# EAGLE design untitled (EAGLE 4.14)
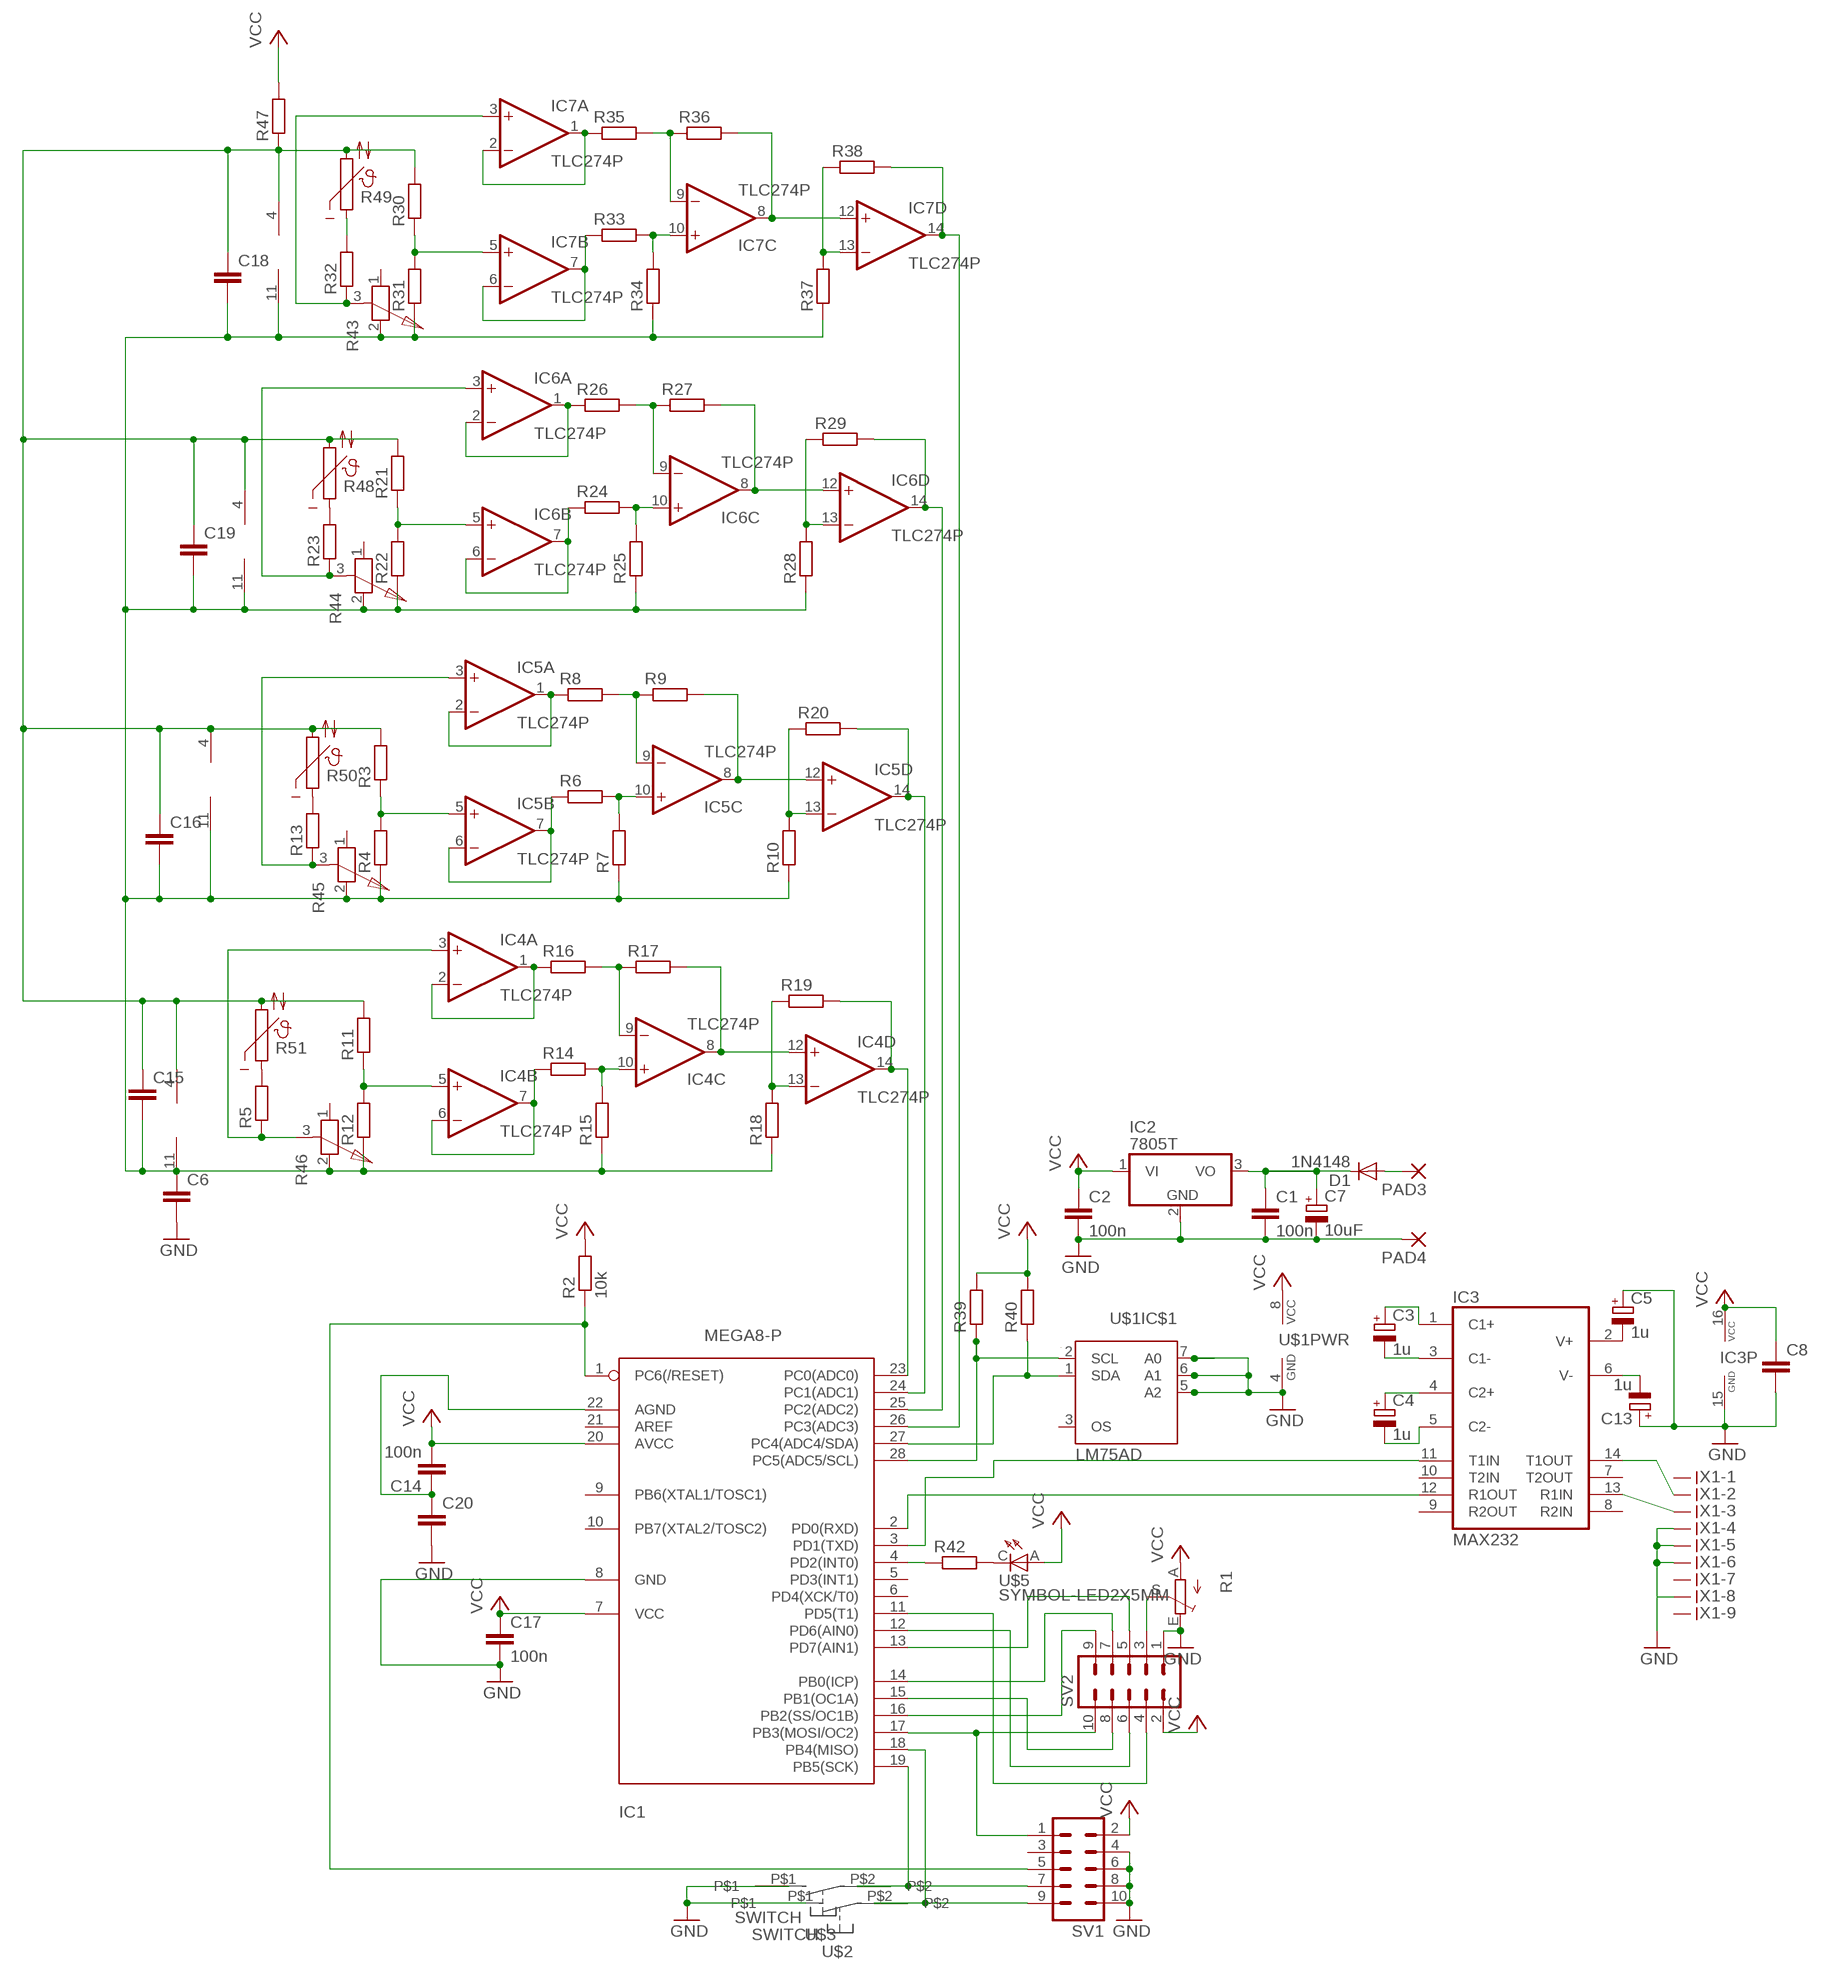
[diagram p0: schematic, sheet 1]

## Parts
C1  100n  C-EUC0805  [C0805]
C2  100n  C-EUC0805  [C0805]
C3  1u  CPOL-EUE2.5-5  [E2,5-5]
C4  1u  CPOL-EUE2.5-5  [E2,5-5]
C5  1u  CPOL-EUE2.5-5  [E2,5-5]
C6  C-EUC0402  [C0402]
C7  10uF  CPOL-EUE5-10.5  [E5-10,5]
C8  C-EUC0805  [C0805]
C13  1u  CPOL-EUE2.5-5  [E2,5-5]
C14  100n  C-EUC0805  [C0805]
C15  C-EUC0805  [C0805]
C16  C-EUC0805  [C0805]
C17  100n  C-EUC0805  [C0805]
C18  C-EUC0805  [C0805]
C19  C-EUC0805  [C0805]
C20  C-EUC0402  [C0402]
D1  1N4148  [DO35-10]
IC1  MEGA8-P  [DIL28-3]
IC2  7805T  [TO220H]
IC3  MAX232  [DIL16]
IC4  TLC274P  [DIL14]
IC5  TLC274P  [DIL14]
IC6  TLC274P  [DIL14]
IC7  TLC274P  [DIL14]
PAD3  3,81/1,4  [3,81/1,4]
PAD4  3,81/1,4  [3,81/1,4]
R1  TRIM_EU-LI10  [LI10]
R2  10k  R-EU_R1206  [R1206]
R3  R-EU_R1206W  [R1206W]
R4  R-EU_R1206W  [R1206W]
R5  R-EU_R1206  [R1206]
R6  R-EU_0309/10  [0309/10]
R7  R-EU_0309/10  [0309/10]
R8  R-EU_0309/10  [0309/10]
R9  R-EU_0309/10  [0309/10]
R10  R-EU_0309/10  [0309/10]
R11  R-EU_R1206W  [R1206W]
R12  R-EU_R1206W  [R1206W]
R13  R-EU_R1206  [R1206]
R14  R-EU_0309/10  [0309/10]
R15  R-EU_0309/10  [0309/10]
R16  R-EU_0309/10  [0309/10]
R17  R-EU_0309/10  [0309/10]
R18  R-EU_0309/10  [0309/10]
R19  R-EU_0309/10  [0309/10]
R20  R-EU_0309/10  [0309/10]
R21  R-EU_R1206W  [R1206W]
R22  R-EU_R1206W  [R1206W]
R23  R-EU_R1206W  [R1206W]
R24  R-EU_0309/10  [0309/10]
R25  R-EU_0309/10  [0309/10]
R26  R-EU_0309/10  [0309/10]
R27  R-EU_0309/10  [0309/10]
R28  R-EU_0309/10  [0309/10]
R29  R-EU_0309/10  [0309/10]
R30  R-EU_R1206W  [R1206W]
R31  R-EU_R1206W  [R1206W]
R32  R-EU_R1206W  [R1206W]
R33  R-EU_0309/10  [0309/10]
R34  R-EU_0309/10  [0309/10]
R35  R-EU_0309/10  [0309/10]
R36  R-EU_0309/10  [0309/10]
R37  R-EU_0309/10  [0309/10]
R38  R-EU_0309/10  [0309/10]
R39  R-EU_0207/7  [0207/7]
R40  R-EU_0207/7  [0207/7]
R42  R-EU_R1206  [R1206]
R43  POT-L  [PT-10]
R44  POT-L  [PT-10]
R45  POT-L  [PT-10]
R46  POT-L  [PT-10]
R47  R-EU_R1206W  [R1206W]
R48  NTC640  [P640]
R49  NTC640  [P640]
R50  NTC640  [P640]
R51  NTC640  [P640]
SV1  ML10  [ML10]
SV2  ML10  [ML10]
U$1  LM75AD  [SO08]
U$2  SWITCH  [SWITCH]
U$3  SWITCH  [SWITCH]
U$5  SYMBOL-LED2X5MM  [LED2X5MM]
X1  F09HS  [F09H]

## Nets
GND: C1.2 C2.2 C5.+ C6.2 C7.- C8.2 C13.+ C17.2 C20.2 IC1.8(GND) IC2.2(GND) IC3.15(GND) PAD4.1(P) R1.E SV1.4 SV1.6 SV1.8 SV1.10 SV2.1 U$1.4(PWR:GND) U$1.5(IC$1:A2) U$1.6(IC$1:A1) U$1.7(IC$1:A0) U$2.P$1 U$3.P$1 X1.4 X1.5 X1.6 X1.8
N$1: IC1.4(PD2(INT0)) R42.1
N$2: C1.1 C7.+ D1.C IC2.3(VO)
N$3: R23.2 R48.1
N$4: IC1.1(PC6(/RESET)) R2.1 SV1.5
N$5: C13.- IC3.6(V-)
N$6: C5.- IC3.2(V+)
N$7: C3.- IC3.3(C1-)
N$8: C4.+ IC3.4(C2+)
N$9: C4.- IC3.5(C2-)
N$10: C3.+ IC3.1(C1+)
N$11: C14.1 C20.1 IC1.22(AGND)
N$12: IC1.2(PD0(RXD)) IC3.12(R1OUT)
N$13: IC3.14(T1OUT) X1.2
N$14: IC3.13(R1IN) X1.3
N$15: IC1.27(PC4(ADC4/SDA)) R40.1 U$1.1(IC$1:SDA)
N$16: IC1.3(PD1(TXD)) IC3.11(T1IN)
N$17: IC5.5(B:+IN) R3.1 R4.2
N$18: IC5.10(C:+IN) R6.2 R7.2
N$19: IC4.5(B:+IN) R11.1 R12.2
N$20: IC4.10(C:+IN) R14.2 R15.2
N$21: IC4.9(C:-IN) R16.2 R17.1
N$22: IC4.8(C:OUT) IC4.12(D:+IN) R17.2
N$23: R1.S SV2.3
N$24: IC4.1(A:OUT) IC4.2(A:-IN) R16.1
N$25: IC4.6(B:-IN) IC4.7(B:OUT) R14.1
N$26: IC1.18(PB4(MISO)) SV1.9 U$2.P$2
N$27: IC4.13(D:-IN) R18.2 R19.1
N$28: IC1.23(PC0(ADC0)) IC4.14(D:OUT) R19.2
N$29: IC1.17(PB3(MOSI/OC2)) SV1.1 SV2.10
N$30: IC5.9(C:-IN) R8.2 R9.1
N$31: R32.2 R49.1
N$32: IC1.11(PD5(T1)) SV2.4
N$33: IC1.12(PD6(AIN0)) SV2.6
N$34: IC1.13(PD7(AIN1)) SV2.5
N$35: IC1.14(PB0(ICP)) SV2.7
N$36: IC1.15(PB1(OC1A)) SV2.8
N$37: IC1.16(PB2(SS/OC1B)) SV2.9
N$38: IC4.3(A:+IN) R5.1 R46.3
N$39: IC5.8(C:OUT) IC5.12(D:+IN) R9.2
N$40: IC5.1(A:OUT) IC5.2(A:-IN) R8.1
N$41: IC5.6(B:-IN) IC5.7(B:OUT) R6.1
N$42: IC5.13(D:-IN) R10.2 R20.1
N$43: IC5.3(A:+IN) R13.1 R45.3
N$44: IC1.24(PC1(ADC1)) IC5.14(D:OUT) R20.2
N$45: IC6.5(B:+IN) R21.1 R22.2
N$46: IC6.10(C:+IN) R24.2 R25.2
N$47: IC6.9(C:-IN) R26.2 R27.1
N$48: IC6.8(C:OUT) IC6.12(D:+IN) R27.2
N$49: IC6.1(A:OUT) IC6.2(A:-IN) R26.1
N$50: IC6.6(B:-IN) IC6.7(B:OUT) R24.1
N$51: IC6.13(D:-IN) R28.2 R29.1
N$52: IC6.3(A:+IN) R23.1 R44.3
N$53: IC1.25(PC2(ADC2)) IC6.14(D:OUT) R29.2
N$54: IC7.5(B:+IN) R30.1 R31.2
N$55: IC7.10(C:+IN) R33.2 R34.2
N$56: IC7.9(C:-IN) R35.2 R36.1
N$57: IC7.8(C:OUT) IC7.12(D:+IN) R36.2
N$58: IC7.1(A:OUT) IC7.2(A:-IN) R35.1
N$59: IC7.6(B:-IN) IC7.7(B:OUT) R33.1
N$60: IC7.13(D:-IN) R37.2 R38.1
N$61: IC7.3(A:+IN) R32.1 R43.3
N$62: IC1.26(PC3(ADC3)) IC7.14(D:OUT) R38.2
N$64: IC1.28(PC5(ADC5/SCL)) R39.1 U$1.2(IC$1:SCL)
N$65: C6.1 C15.2 C16.2 C18.2 C19.2 IC4.11(P:V-) IC5.11(P:V-) IC6.11(P:V-) IC7.11(P:V-) R4.1 R7.1 R10.1 R12.1 R15.1 R18.1 R22.1 R25.1 R28.1 R31.1 R34.1 R37.1 R43.2 R44.2 R45.2 R46.2
N$67: IC1.19(PB5(SCK)) SV1.7 U$3.P$2
N$68: D1.A PAD3.1(P)
N$69: R42.2 U$5.C
N$70: R13.2 R50.1
N$71: R5.2 R51.1
N$72: C15.1 C16.1 C18.1 C19.1 IC4.4(P:V+) IC5.4(P:V+) IC6.4(P:V+) IC7.4(P:V+) R3.2 R11.2 R21.2 R30.2 R47.1 R48.2 R49.2 R50.2 R51.2
VCC: C2.1 C8.1 C14.2 C17.1 IC1.7(VCC) IC1.20(AVCC) IC2.1(VI) IC3.16(VCC) R1.A R2.2 R39.2 R40.2 R47.2 SV1.2 SV2.2 U$1.8(PWR:VCC) U$5.A
Unconnected: IC1.5(PD3(INT1)) IC1.6(PD4(XCK/T0)) IC1.9(PB6(XTAL1/TOSC1)) IC1.10(PB7(XTAL2/TOSC2)) IC1.21(AREF) IC3.7(T2OUT) IC3.8(R2IN) IC3.9(R2OUT) IC3.10(T2IN) R43.1 R44.1 R45.1 R46.1 SV1.3 U$1.3(IC$1:OS) X1.1 X1.7 X1.9

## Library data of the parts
C1 C2 C6 C8 C14-C20 = rcl:C-EU: CAPACITOR, European symbol
C3-C5 C7 C13 = rcl:CPOL-EU: POLARIZED CAPACITOR, European symbol
D1 = diode:1N4148: DIODE
IC1 = avr:MEGA8-P: MICROCONTROLLER 8 Kbytes FLASH 1 kbytes SRAM 512 bytes EEPROM USART 4-channel 10 bit ADC 2-channel 8 bit ADC
IC2 = linear:78*: Positive VOLTAGE REGULATOR
IC3 = maxim:MAX232: RS232 TRANSEIVER
IC4-IC7 = linear:TLC274: OP AMP
PAD3 PAD4 = wirepad:3,81/1,4: THROUGH-HOLE PAD
R1 = pot:TRIM_EU-: POTENTIOMETER
R2-R40 R42 R47 = rcl:R-EU_: RESISTOR, European symbol
R43-R46 = discrete:POT-L
R48-R51 = ptc-ntc:NTC640: PHILIPS NTC
SV1 SV2 = con-harting-ml:ML10: HARTING
U$1 = i2c:LM75AD: Digital Temperature Sensor and Thermal Watchdog
U$2 U$3 = MicrocontrollerPraktikum:SWITCH
U$5 = MicrocontrollerPraktikum:SYMBOL-LED2X5MM
X1 = con-subd:F09?S: SUB-D

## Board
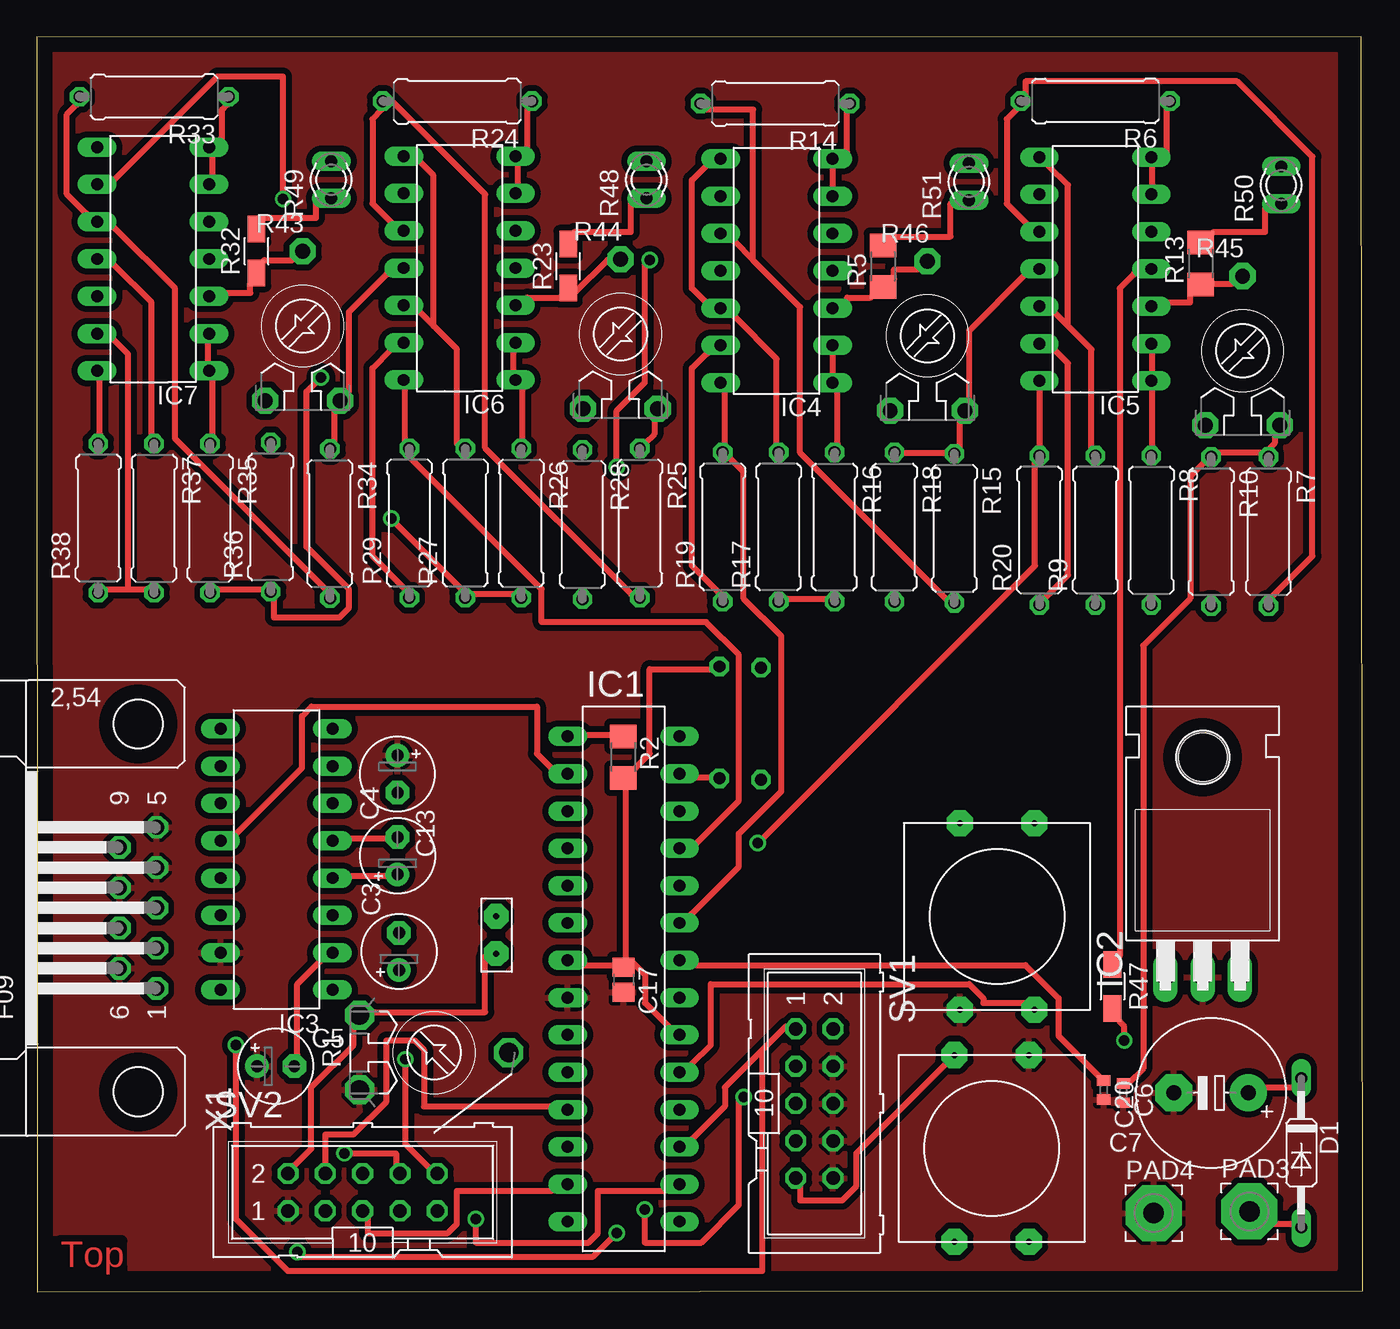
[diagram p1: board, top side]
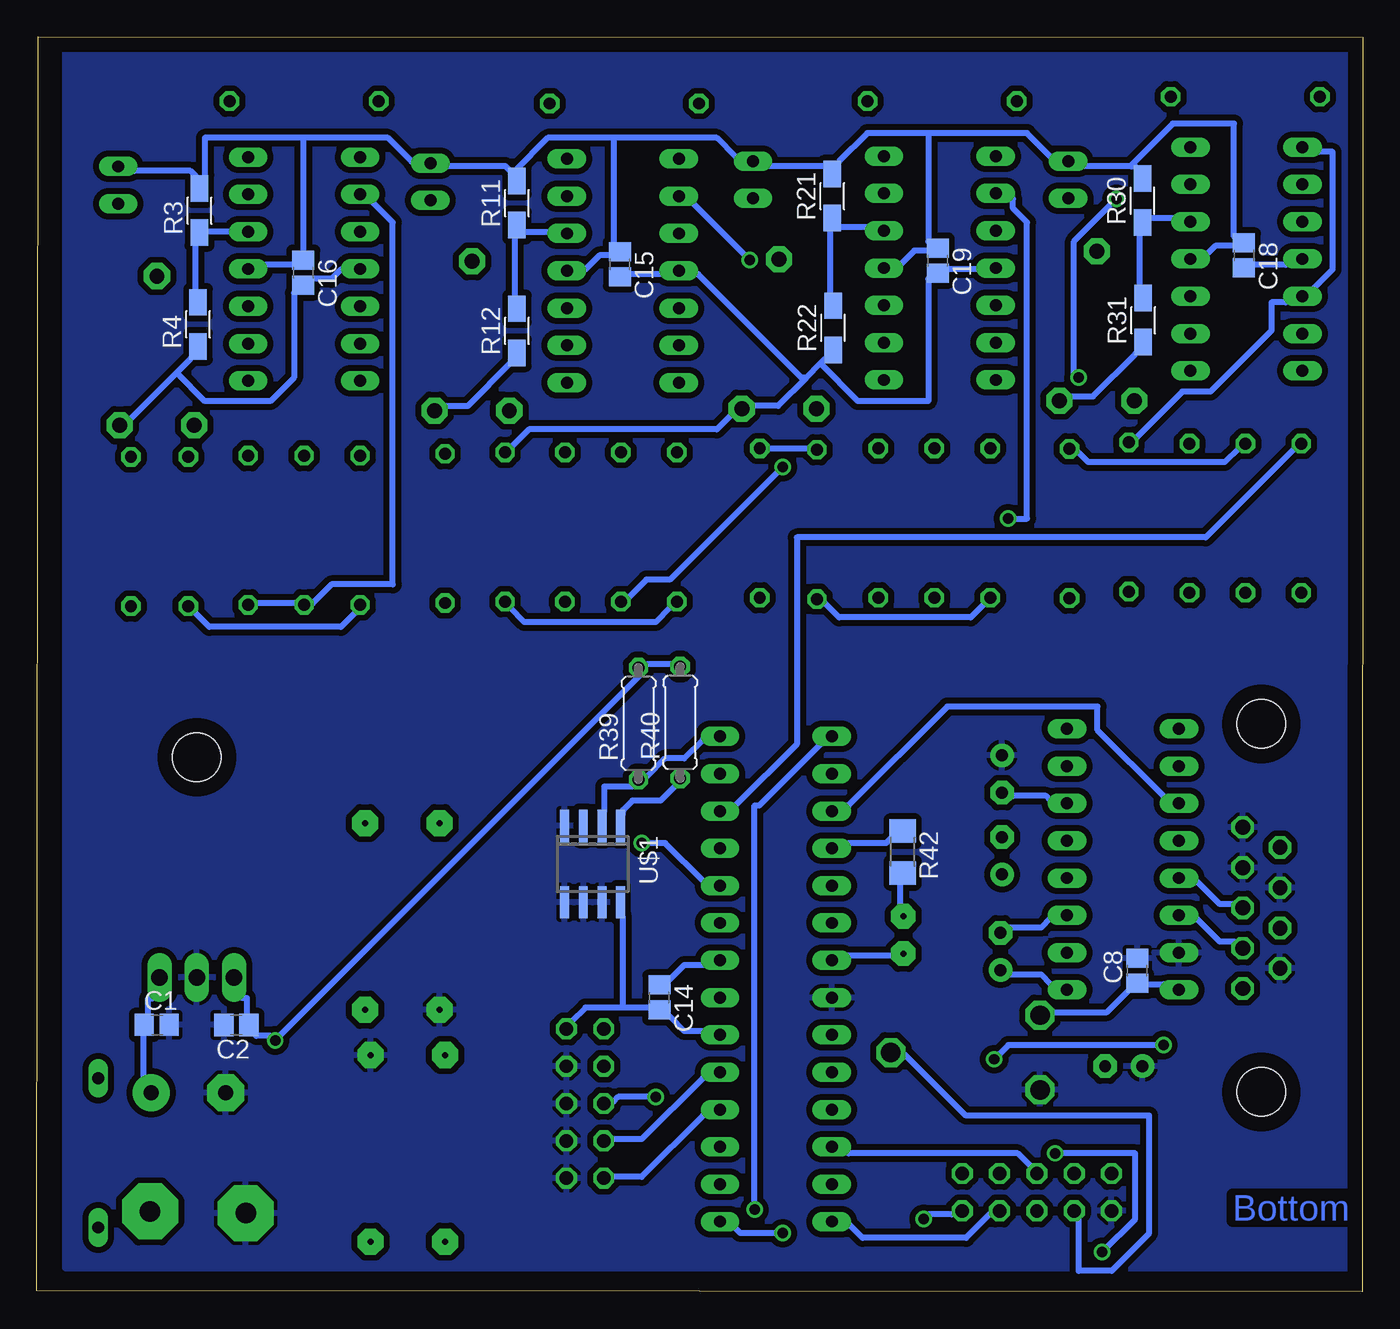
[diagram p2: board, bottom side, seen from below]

Size 90.3 x 85.43 mm. Coordinates in mm from the lower left corner, seen from the top.
Outline: 0.04,0 90.3,0.06 90.21,85.43 0,85.41 0.04,0
Copper layers (1*16): Top 0mm / dielectric 1.5mm / Bottom 0.035mm
Design rules "default": minimum track width 16mil, minimum drill 28mil, track to track 16mil, track to pad 16mil, pad to pad 16mil, via to via 16mil, smd to smd 16mil, copper to edge 40mil, drill to drill 8mil, minimum pad ring 10mil, minimum via ring 8mil, stop-mask expansion 4mil, vias tented up to drill 0mil, thermal gap 10mil

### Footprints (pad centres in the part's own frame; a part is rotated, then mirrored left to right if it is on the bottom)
C0805 = smd 1.3 x 1.5: 1 -0.85,0; 2 0.85,0
E2,5-5 = drill 0.813 pad 1.6 round: + -1.27,0 | drill 0.813 pad 1.6 octagon: - 1.27,0
C0402 = smd 0.7 x 0.9: 1 -0.65,0; 2 0.65,0
E5-10,5 = drill 1.016 pad 2.54 round: + -2.54,0 | drill 1.016 pad 2.54 octagon: - 2.54,0
DO35-10 = drill 0.813 long: A 5.08,0; C -5.08,0
DIL28-3 = drill 0.813 long: 1 -16.51,-3.81; 2 -13.97,-3.81; 3 -11.43,-3.81; 4 -8.89,-3.81; 5 -6.35,-3.81; 6 -3.81,-3.81; 7 -1.27,-3.81; 8 1.27,-3.81; 9 3.81,-3.81; 10 6.35,-3.81; 11 8.89,-3.81; 12 11.43,-3.81; 13 13.97,-3.81; 14 16.51,-3.81; 15 16.51,3.81; 16 13.97,3.81; 17 11.43,3.81; 18 8.89,3.81; 19 6.35,3.81; 20 3.81,3.81; 21 1.27,3.81; 22 -1.27,3.81; 23 -3.81,3.81; 24 -6.35,3.81; 25 -8.89,3.81; 26 -11.43,3.81; 27 -13.97,3.81; 28 -16.51,3.81
TO220H = drill 1.118 long: 1 -2.54,-10.16; 2 0,-10.16; 3 2.54,-10.16 | hole 3.302: 0,4.826
DIL16 = drill 0.813 long: 1 -8.89,-3.81; 2 -6.35,-3.81; 3 -3.81,-3.81; 4 -1.27,-3.81; 5 1.27,-3.81; 6 3.81,-3.81; 7 6.35,-3.81; 8 8.89,-3.81; 9 8.89,3.81; 10 6.35,3.81; 11 3.81,3.81; 12 1.27,3.81; 13 -1.27,3.81; 14 -3.81,3.81; 15 -6.35,3.81; 16 -8.89,3.81
DIL14 = drill 0.813 long: 1 -7.62,-3.81; 2 -5.08,-3.81; 3 -2.54,-3.81; 4 0,-3.81; 5 2.54,-3.81; 6 5.08,-3.81; 7 7.62,-3.81; 8 7.62,3.81; 9 5.08,3.81; 10 2.54,3.81; 11 0,3.81; 12 -2.54,3.81; 13 -5.08,3.81; 14 -7.62,3.81
3,81/1,4 = drill 1.397 pad 3.81 octagon: 1 0,0
LI10 = drill 1.321 octagon: A -2.54,-5.08; E 2.54,-5.08; S 0,5.08
R1206 = smd 1.6 x 1.803: 1 -1.422,0; 2 1.422,0
R1206W = smd 1.8 x 1.2: 1 -1.499,0; 2 1.499,0
0309/10 = drill 0.813 octagon: 1 -5.08,0; 2 5.08,0
0207/7 = drill 0.813 octagon: 1 -3.81,0; 2 3.81,0
PT-10 = drill 1.016 pad 1.778 octagon: 1 -2.54,-5.08; 2 2.54,-5.08; 3 0,5.08
P640 = drill 0.813 long: 1 -1.27,0; 2 1.27,0
ML10 = drill 0.914 octagon: 1 -5.08,-1.27; 2 -5.08,1.27; 3 -2.54,-1.27; 4 -2.54,1.27; 5 0,-1.27; 6 0,1.27; 7 2.54,-1.27; 8 2.54,1.27; 9 5.08,-1.27; 10 5.08,1.27
SO08 = smd 0.6 x 2.2: 1 -1.905,-2.6; 2 -0.635,-2.6; 3 0.635,-2.6; 4 1.905,-2.6; 5 1.905,2.6; 6 0.635,2.6; 7 -0.635,2.6; 8 -1.905,2.6
SWITCH = drill 0.406 pad 1.778 octagon: P$1 -2.54,-6.35; P$2 2.54,-6.35; P$3 2.54,6.35; P$4 -2.54,6.35
LED2X5MM = drill 0.406 pad 1.676 octagon: A 0,0; C 2.54,0
F09H = drill 1.016 octagon: 1 -5.486,-1.27; 2 -2.743,-1.27; 3 0,-1.27; 4 2.743,-1.27; 5 5.486,-1.27; 6 -4.115,1.27; 7 -1.372,1.27; 8 1.372,1.27; 9 4.115,1.27 | hole 3.302: -12.522,0; 12.522,0

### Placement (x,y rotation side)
C1  82.12,18.17 0 bottom
C2  76.7,18.16 180 bottom
C3  24.68,23.16 90 top
C4  24.57,29.68 90 top
C5  16.28,15.35 0 top
C6  73.98,13.52 270 top
C7  79.97,13.54 180 top
C8  15.36,21.85 90 bottom
C13  24.56,35.24 270 top
C14  47.89,20.04 270 bottom
C15  50.59,69.95 270 bottom
C16  72.15,69.37 270 bottom
C17  39.96,21.25 270 top
C18  8.09,70.55 270 bottom
C19  28.94,70.19 270 bottom
C20  72.65,13.74 270 top
D1  86.1,9.45 270 top
IC1  39.96,21.29 270 top
IC2  79.4,31.56 0 top
IC3  16.33,29.43 90 top
IC4  50.38,69.5 90 top
IC5  72.09,69.62 90 top
IC6  28.8,69.69 90 top
IC7  7.92,70.3 90 top
PAD3  82.57,5.47 0 top
PAD4  76.06,5.36 0 top
R1  27.06,16.28 270 top
R2  39.95,36.39 270 top
R3  79.22,73.61 90 bottom
R4  79.31,65.86 90 bottom
R5  57.62,69.81 90 top
R6  72.09,81.05 180 top
R7  83.88,51.75 270 top
R8  75.9,51.84 270 top
R9  72.09,51.84 90 top
R10  79.98,51.75 270 top
R11  57.6,74.11 90 bottom
R12  57.59,65.42 90 bottom
R13  79.25,70 90 top
R14  50.29,80.89 180 top
R15  62.49,51.97 270 top
R16  54.32,52.06 270 top
R17  50.51,52.06 90 top
R18  58.41,52.06 270 top
R19  46.7,52.06 90 top
R20  68.28,51.84 90 top
R21  36.12,74.58 90 bottom
R22  36.06,65.62 90 bottom
R23  36.19,69.82 90 top
R24  28.64,81.04 180 top
R25  41.07,52.32 270 top
R26  32.99,52.32 270 top
R27  29.18,52.32 90 top
R28  37.17,52.23 270 top
R29  25.37,52.32 90 top
R30  15,74.28 90 bottom
R31  14.95,66.14 90 bottom
R32  14.97,70.85 90 top
R33  7.99,81.35 180 top
R34  19.97,52.3 270 top
R35  11.8,52.66 270 top
R36  15.93,52.74 90 top
R37  7.99,52.66 270 top
R38  4.18,52.66 90 top
R39  49.32,38.68 90 bottom
R40  46.49,38.75 90 bottom
R42  31.33,29.94 270 bottom
R43  18.11,65.74 0 top
R44  39.75,65.2 0 top
R45  82.11,64.06 0 top
R46  60.66,65.06 0 top
R47  73.25,20.77 270 top
R48  41.53,75.7 90 top
R49  20.05,75.69 90 top
R50  84.75,75.33 90 top
R51  63.49,75.55 90 top
SV1  52.96,12.81 270 top
SV2  22.19,6.78 0 top
U$1  52.44,29.11 180 bottom
U$2  65.03,9.76 180 top
U$3  65.39,25.55 0 top
U$5  31.29,23.02 90 top
X1  6.91,26.13 90 top

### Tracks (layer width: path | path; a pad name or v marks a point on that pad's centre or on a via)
GND
  pour Bottom: 0.32,85 88.38,85 88.38,1.6 0.32,1.6 0.32,85
  pour Top: 1.17,84.28 88.4,84.28 88.4,1.59 1.22,1.59 1.22,84.19
N$1
  Bottom 0.406: R42.1 32.14,30.87 32.46,30.55 35.02,30.55 IC1.4
N$2
  Top 0.406: D1.C 85.58,13.91 83.66,13.91 C7.+
  Bottom 0.406: IC2.3 82.38,19.99 82.7,19.99 82.7,18.71 C1.1 83.02,17.43 83.02,14.55 C7.+
N$3
  Top 0.406: R23.2 36.62,72.15 40.46,72.15 40.46,74.07 R48.1
N$4  (via drill 0.71)
  Top 0.406: R2.1 39.18,37.91 37.26,37.91 IC1.1 | v48.14,13.27 47.82,12.95 47.82,5.91 45.26,3.35 41.42,3.35 v41.42,5.59
  Bottom 0.406: v48.14,13.27 50.7,13.27 51.02,12.95 SV1.5 | v41.42,5.59 41.42,33.11 41.1,33.11 36.94,37.27 IC1.1
N$5
  Bottom 0.406: IC3.6 21.26,33.43 21.58,33.75 23.82,33.75 C13.-
N$6
  Top 0.406: IC3.2 19.34,22.55 17.74,20.95 17.74,16.15 C5.-
N$7
  Bottom 0.406: IC3.3 21.26,25.43 21.9,24.79 24.14,24.79 C3.-
N$8
  Top 0.406: IC3.4 21.26,28.31 23.82,28.31 C4.+
N$9
  Top 0.406: IC3.5 21.26,30.87 23.82,30.87 C4.-
N$10
  Bottom 0.406: IC3.1 21.26,20.95 21.9,21.59 24.14,21.59 C3.+
N$11
  Top 0.406: C20.1 72.46,14.55 69.58,17.43 69.58,19.99 67.34,22.23 44.94,22.23 IC1.22
  Bottom 0.406: C14.1 47.18,21.27 46.22,22.23 44.94,22.23 IC1.22
N$12
  Top 0.406: IC3.12 13.58,31.19 18.06,35.67 18.06,39.19 18.7,39.83 34.06,39.83 34.06,36.63 35.02,35.67 IC1.2
N$13
  Bottom 0.406: IC3.14 11.34,25.43 9.74,23.83 8.78,23.83 X1.2
N$14
  Bottom 0.406: IC3.13 11.34,27.99 9.74,26.39 8.78,26.39 X1.3
N$15
  Top 0.406: IC1.27 44.94,35.03 45.9,35.03 R40.1
  Bottom 0.406: U$1.1 50.38,32.79 49.74,33.43 47.82,33.43 46.86,34.39 R40.1
N$16
  Bottom 0.406: IC3.11 13.58,33.75 18.06,38.23 18.06,39.83 28.3,39.83 35.02,33.11 IC1.3
N$17
  Bottom 0.406: R4.2 79.5,67.99 79.5,71.51 R3.1 78.86,72.15 76.94,72.15 IC5.5
N$18
  Top 0.406: R7.2 83.98,47.19 86.86,50.07 86.86,77.27 81.74,82.39 67.34,82.39 67.34,81.43 R6.2 66.7,80.47 66.06,79.83 66.06,74.07 67.34,72.79 IC5.10
N$19
  Bottom 0.406: R12.2 57.74,67.67 57.74,71.83 R11.1 57.1,72.15 55.5,72.15 IC4.5
N$20
  Top 0.406: 48.78,70.23 47.5,71.51 IC4.10 | 48.78,70.23 51.98,67.03 51.98,57.11 61.9,47.19 R15.2 | 48.78,70.23 48.78,80.47 45.58,80.47 R14.2
N$21  (via drill 0.71)
  Top 0.406: R17.1 51.02,47.19 53.9,47.19 R16.2 | v41.74,70.23 41.42,69.91 41.42,61.91 39.5,59.99 v39.5,56.15
  Bottom 0.406: v41.74,70.23 45.58,74.07 IC4.9 | v39.5,56.15 47.18,48.47 48.78,48.47 50.06,47.19 R17.1
N$22
  Top 0.406: R17.2 50.38,57.75 50.38,63.51 47.5,66.39 IC4.12 45.58,67.35 44.62,68.31 44.62,75.67 45.58,76.63 IC4.8
N$23
  Bottom 0.406: SV2.3 19.34,4.95 19.34,1.43 17.1,1.43 14.54,3.99 14.54,11.99 27.02,11.99 31.18,16.15 R1.S
N$24
  Top 0.406: IC4.2 54.22,63.83 54.22,62.23 IC4.1 54.54,61.27 54.54,57.75 R16.1
N$25
  Top 0.406: IC4.6 54.22,75.03 54.22,76.63 IC4.7 55.18,77.59 55.18,80.47 R14.1
N$26
  Top 0.406: U$2.P$2 61.9,15.51 55.82,9.43 55.82,7.19 54.86,6.23 51.98,6.23 51.98,7.19 SV1.9
  Bottom 0.406: IC1.18 44.94,11.99 49.1,7.83 51.02,7.83 SV1.9
N$27
  Top 0.406: IC4.13 45.58,63.83 44.62,62.87 44.62,49.43 46.54,47.51 R19.1
  Bottom 0.406: R19.1 47.18,46.55 48.14,45.59 57.1,45.59 58.06,46.55 R18.2
N$28
  Top 0.406: IC1.23 44.62,25.75 47.82,28.95 47.82,31.19 50.7,34.07 50.7,44.63 48.14,47.19 48.14,55.83 47.18,56.79 R19.2 46.86,57.75 46.86,61.27 IC4.14
N$29  (via drill 0.71)
  Top 0.406: 49.42,16.47 51.02,18.07 SV1.1 | 49.42,16.47 46.86,13.91 46.86,12.63 44.62,10.39 IC1.17 | v25.1,15.83 25.1,10.07 26.7,8.47 SV2.10 | v13.58,16.79 13.58,4.95 17.1,1.43 49.42,1.43 49.42,16.47
  Bottom 0.406: v25.1,15.83 24.14,16.79 v13.58,16.79
N$30
  Bottom 0.406: R8.2 75.34,46.87 72.46,46.87 R9.1 71.5,46.87 70.22,48.15 66.06,48.15 66.06,72.79 67.34,74.07 IC5.9
N$31
  Top 0.406: R32.2 15.5,73.11 19.02,73.11 19.02,74.07 R49.1
N$32
  Top 0.406: IC1.11 35.02,12.63 26.38,12.63 26.38,16.47 25.74,17.11 23.82,17.11 23.82,12.95 21.58,10.71 19.66,10.71 19.66,8.47 SV2.4
N$33
  Bottom 0.406: IC1.12 35.02,9.43 23.5,9.43 22.54,8.47 SV2.6
N$34
  Top 0.406: IC1.13 35.02,6.87 28.62,6.87 28.62,4.63 27.98,3.99 22.54,3.99 22.54,4.95 SV2.5
N$35
  Bottom 0.406: IC1.14 35.02,4.63 34.06,3.67 27.02,3.67 25.42,5.27 SV2.7
N$36  (via drill 0.71)
  Top 0.406: v39.5,3.99 37.9,2.39 17.74,2.39 v17.74,2.71 | v20.94,9.43 24.46,9.43 24.46,8.47 SV2.8
  Bottom 0.406: v39.5,3.99 42.38,3.99 42.7,4.31 IC1.15 | v17.74,2.71 15.5,4.95 15.5,9.43 v20.94,9.43
N$37  (via drill 0.71)
  Top 0.406: v29.9,4.95 29.9,3.35 37.58,3.35 38.22,3.99 38.22,6.87 42.7,6.87 IC1.16
  Bottom 0.406: v29.9,4.95 29.58,5.27 27.98,5.27 SV2.9
N$38
  Top 0.406: IC4.3 55.18,67.35 55.18,67.67 56.78,67.67 R5.1 58.38,68.95 58.38,69.59 59.98,69.59 R46.3
N$39
  Top 0.406: 70.22,65.75 71.82,64.15 71.82,57.43 R9.2 | 70.22,65.75 69.26,66.71 IC5.12 | 70.22,65.75 70.22,75.35 68.94,76.63 IC5.8
N$40
  Top 0.406: R8.1 75.98,57.43 75.98,61.59 IC5.1 75.98,62.55 75.98,64.15 IC5.2
N$41
  Top 0.406: IC5.6 75.98,75.35 75.98,76.63 IC5.7 76.94,77.59 76.94,80.47 R6.1
N$42
  Top 0.406: IC5.13 69.26,64.15 70.22,63.19 70.22,48.79 68.62,47.19 R20.1
  Bottom 0.406: R20.1 68.62,46.23 69.58,45.27 78.54,45.27 79.5,46.23 R10.2
N$43
  Top 0.406: R45.3 81.42,68.63 80.14,68.63 R13.1 78.54,67.99 78.54,67.35 76.94,67.35 IC5.3
N$44  (via drill 0.71)
  Top 0.406: v49.1,30.55 67.98,49.43 67.98,56.47 R20.2 68.3,57.43 68.3,61.59 IC5.14
  Bottom 0.406: v49.1,30.55 47.5,30.55 44.94,27.99 IC1.24
N$45
  Bottom 0.406: R22.2 36.3,67.99 36.3,72.47 R21.1 35.66,72.47 33.74,72.47 IC6.5
N$46
  Top 0.406: R25.2 40.46,47.51 30.54,57.43 30.54,74.71 24.14,81.11 R24.2 23.5,80.47 22.86,79.83 22.86,74.07 24.14,72.79 IC6.10
N$47  (via drill 0.71)
  Top 0.406: R26.2 32.46,47.51 29.58,47.51 R27.1 28.94,47.83 v24.14,52.63
  Bottom 0.406: v24.14,52.63 22.86,52.63 22.86,72.79 23.82,73.75 23.82,74.39 IC6.9
N$48
  Top 0.406: 27.02,65.75 28.62,64.15 28.62,57.75 R27.2 | 27.02,65.75 26.06,66.71 IC6.12 | 27.02,65.75 27.02,75.99 26.06,76.95 IC6.8
N$49
  Top 0.406: IC6.2 32.46,64.15 32.46,62.55 IC6.1 33.1,61.59 33.1,57.75 R26.1
N$50
  Top 0.406: IC6.6 32.78,75.35 32.78,76.95 IC6.7 33.42,77.91 33.42,80.47 R24.1
N$51
  Top 0.406: IC6.13 24.14,64.15 22.86,62.87 22.86,50.07 25.1,47.83 R29.1
  Bottom 0.406: R28.2 36.62,46.87 35.66,45.91 26.7,45.91 25.74,46.87 R29.1
N$52
  Top 0.406: IC6.3 33.42,67.67 35.66,67.67 R23.1 36.62,67.99 38.86,70.23 R44.3
N$53
  Top 0.406: IC1.25 44.94,30.55 47.82,33.43 47.82,43.35 45.58,45.59 34.38,45.59 34.38,47.83 25.42,56.79 R29.2 25.1,57.75 25.1,61.59 IC6.14
N$54
  Bottom 0.406: R31.2 15.18,68.31 15.18,72.15 R30.1 14.54,73.11 12.94,73.11 IC7.5
N$55
  Top 0.406: R34.2 19.66,47.83 9.42,58.07 9.42,68.31 5.26,72.47 IC7.10 3.34,73.43 2.06,74.71 2.06,80.15 2.7,80.79 R33.2
N$56  (via drill 0.71)
  Top 0.406: R35.2 12.3,47.83 15.5,47.83 R36.1 16.14,47.19 16.14,45.91 20.62,45.91 21.26,46.55 21.26,47.83 18.38,50.71 18.38,61.27 v19.34,62.23 | v16.78,74.39 16.78,82.71 12.3,82.71 5.26,75.67 IC7.9
  Bottom 0.406: v16.78,74.39 19.66,71.51 19.66,62.23 v19.34,62.23
N$57
  Bottom 0.406: IC7.8 3.02,77.59 2.06,77.59 2.06,69.59 3.34,68.31 IC7.12 5.26,67.35 6.22,67.35 6.22,65.43 10.38,61.27 12.3,61.27 15.5,58.07 R36.2
N$58
  Top 0.406: IC7.2 11.66,64.79 11.66,63.19 IC7.1 11.98,62.23 11.98,58.39 R35.1
N$59
  Top 0.406: IC7.6 11.98,75.99 11.98,77.27 IC7.7 12.62,78.55 12.62,80.47 12.94,80.79 R33.1
N$60
  Top 0.406: 6.22,47.83 7.5,47.83 R37.2 | 6.22,47.83 4.62,47.83 R38.1 | 6.22,47.83 6.22,63.83 5.26,64.79 IC7.13
N$61
  Top 0.406: R43.3 17.42,70.55 17.42,70.23 15.5,70.23 R32.1 14.54,68.63 14.54,67.99 12.94,67.99 IC7.3
N$62
  Top 0.406: R38.2 4.3,58.39 4.3,62.23 IC7.14
  Bottom 0.406: IC1.26 42.7,33.11 38.54,37.27 38.54,51.35 10.7,51.35 4.62,57.43 R38.2
N$64
  Bottom 0.406: U$1.2 51.66,32.79 51.66,34.39 49.74,34.39 R39.1 48.78,35.03 47.5,36.31 46.22,36.31 44.94,37.59 IC1.28
N$65
  Top 0.406: R45.2 84.3,58.39 84.3,57.75 83.98,57.43 R7.1 83.34,57.11 80.46,57.11 R10.1 79.5,56.47 78.54,55.51 78.54,47.19 75.34,43.99 75.34,15.19 74.38,14.23 C6.1 | R34.1 20.3,57.75 20.3,59.99 R43.2 21.26,61.27 21.26,66.71 23.82,69.27 IC6.11 | IC7.11 5.26,69.91 7.82,67.35 7.82,58.39 R37.1 | R25.1 41.42,57.75 42.06,58.39 42.06,59.35 R44.2 | R18.1 59.02,57.11 61.9,57.11 R15.1 62.86,57.43 62.86,59.35 R46.2 63.5,60.63 63.5,65.43 67.34,69.27 IC5.11
  Bottom 0.406: 80.78,62.55 83.98,59.35 R45.2 | 80.78,62.55 79.82,63.51 R4.1 | C18.2 7.5,69.91 5.26,69.91 IC7.11 | IC6.11 26.06,69.59 28.3,69.59 C19.2 29.58,68.95 29.58,60.63 34.38,60.63 36.94,63.19 | R31.1 15.5,63.83 18.38,60.95 19.98,60.95 R43.2 | R37.1 8.46,57.43 9.42,56.47 18.7,56.47 19.34,57.11 R34.1 | R28.1 37.58,57.43 40.46,57.43 R25.1 | C15.2 50.06,69.27 47.82,69.27 IC4.11 45.26,69.27 38.22,62.23 37.9,62.23 | 37.9,62.23 39.82,60.31 41.42,60.31 R44.2 43.02,59.67 43.98,58.71 56.78,58.71 58.06,57.43 R18.1 | 36.94,63.19 37.9,62.23 | 36.94,63.19 36.62,63.51 R22.1 | IC5.11 69.58,69.59 70.22,68.95 71.5,68.95 C16.2 72.78,67.99 72.78,62.23 74.38,60.63 78.86,60.63 80.78,62.55 | R12.1 58.06,63.19 60.94,60.31 62.54,60.31 R46.2
N$67
  Top 0.406: U$3.P$2 67.34,19.67 64.46,19.67 64.46,19.99 63.5,20.95 45.9,20.95 45.9,16.79 44.62,15.51 IC1.19
  Bottom 0.406: IC1.19 44.94,14.55 49.1,10.39 51.02,10.39 SV1.7
N$68
  Top 0.406: D1.A 85.58,4.63 84.3,4.63 PAD3.1
N$69
  Bottom 0.406: R42.2 31.5,27.99 31.5,26.39 U$5.C
N$70
  Top 0.406: R13.2 80.14,72.15 83.66,72.15 83.66,73.75 R50.1
N$71
  Top 0.406: R5.2 58.38,71.83 62.22,71.83 62.22,74.07 R51.1
N$72
  Top 0.406: R47.1 73.74,22.87 73.74,68.31 74.7,69.27 IC5.4
  Bottom 0.406: IC5.4 74.7,69.91 72.78,69.91 C16.1 72.14,70.87 72.14,78.55 | IC7.4 10.7,70.55 10.06,71.19 8.78,71.19 C18.1 8.78,71.83 8.78,79.51 12.94,79.51 15.82,76.63 | 15.82,76.63 19.02,76.63 R49.2 21.26,77.27 22.86,78.87 29.58,78.87 | 15.82,76.63 15.5,76.63 R30.2 | IC6.4 31.5,69.91 30.54,70.87 29.58,70.87 C19.1 29.58,71.51 29.58,78.87 | 29.58,78.87 33.74,78.87 35.66,76.95 R21.2 36.62,76.63 40.46,76.63 R48.2 42.7,77.27 43.98,78.55 51.02,78.55 | R50.2 83.66,76.31 79.82,76.31 79.5,75.99 R3.2 78.86,75.99 78.86,78.55 72.14,78.55 | IC4.4 52.94,69.59 51.98,70.55 51.02,70.55 C15.1 51.02,71.19 51.02,78.55 | 51.02,78.55 55.5,78.55 57.74,76.31 R11.2 58.06,76.31 58.38,76.63 62.22,76.63 R51.2 64.78,76.95 66.38,78.55 72.14,78.55
VCC  (via drill 0.71)
  Top 0.406: SV2.2 17.42,8.47 18.7,9.75 18.7,13.91 21.58,16.79 21.58,18.07 R1.A 22.86,19.03 30.54,19.03 30.54,22.87 U$5.A | v74.06,17.11 74.06,18.07 73.74,18.39 R47.2 | C17.1 39.5,22.23 37.26,22.23 IC1.7 | C17.1 40.14,22.55 40.14,34.39 R2.2 40.78,35.67 41.74,36.63 41.74,42.39 45.9,42.39 R40.2 | IC1.20 43.02,18.07 41.42,19.67 41.42,21.59 40.46,22.55 C17.1
  Bottom 0.406: IC3.16 13.58,20.95 14.86,20.95 C8.1 15.82,20.63 17.42,19.03 21.26,19.03 R1.A | IC1.20 44.94,17.75 46.22,17.75 47.18,18.71 C14.2 48.46,19.35 50.38,19.35 | 50.38,19.35 50.38,25.43 U$1.8 | 50.38,19.35 52.94,19.35 53.9,18.39 SV1.2 | IC2.1 76.3,19.99 75.98,19.99 75.98,18.71 C2.1 75.34,17.43 74.38,17.43 v74.06,17.11 49.1,42.07 R39.2 48.78,42.71 46.86,42.71 R40.2 | U$5.A 31.82,22.87 35.02,22.87 IC1.7

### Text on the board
Top: Top
Bottom: Bottom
